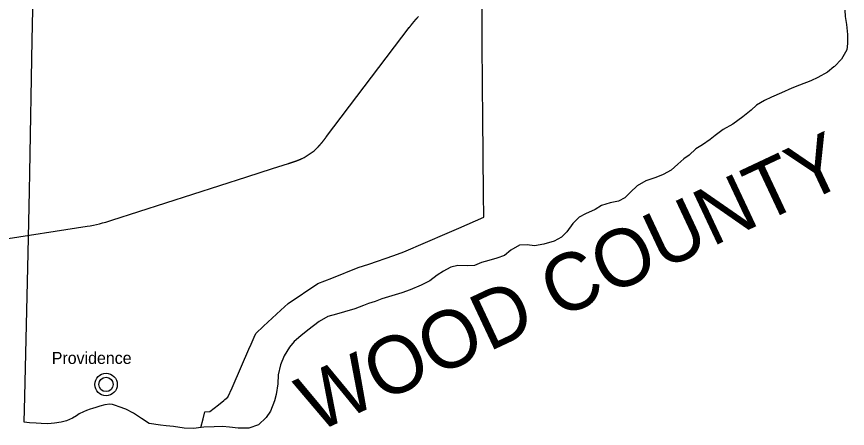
# Model space of a CAD drawing. Extents: x 0 to 750, y 0 to 507.
# Drawn here: x 114.5 to 187.1, y 53 to 88.9 of the extents above; entities that cross this region are included whole.
import ezdxf

# ---------------------------------------------------------------- set-up
doc = ezdxf.new("R2010")
doc.units = 0
for name, color, linetype in [('DV_X_Corp_Line', 7, 'Continuous'), ('GM_X_Adjacent_County_Text', 7, 'Continuous'), ('GM_X_County', 7, 'Continuous'), ('GM_X_State_Route', 7, 'Continuous'), ('GM_X_US_Route', 7, 'Continuous')]:
    doc.layers.add(name, color=color, linetype=linetype)

msp = doc.modelspace()

# ---------------------------------------------------------------- linework, layer by layer
at = {"layer": 'DV_X_Corp_Line'}
for radius in [0.982, 0.623]:
    msp.add_circle((122.35, 56.813), radius, dxfattribs=at)
at = {"layer": 'GM_X_County'}
msp.add_lwpolyline([(186.881, 89.488), (186.896, 88.92), (187.006, 88.235), (187.096, 87.36), (187.093, 86.581), (187.054, 86.01), (186.583, 85.214), (185.975, 84.582), (185.911, 84.53), (185.368, 84.085), (184.526, 83.617), (183.908, 83.307), (182.922, 82.952), (182.234, 82.672), (181.343, 82.281), (180.472, 81.884), (179.864, 81.598), (179.164, 81.184), (178.684, 80.755), (177.966, 80.165), (177.086, 79.533), (176.239, 79.075), (175.557, 78.555), (175.124, 78.206), (174.443, 77.731), (173.864, 77.374), (173.287, 76.842), (172.814, 76.504), (172.274, 76.036), (171.693, 75.524), (171.003, 75.145), (170.36, 74.875), (169.486, 74.584), (168.735, 74.15), (168.163, 73.593), (167.647, 73.09), (167.12, 72.813), (166.378, 72.66), (165.631, 72.432), (165.057, 72.071), (164.222, 71.714), (163.674, 71.413), (163.112, 70.851), (162.582, 70.127), (162.138, 69.683), (161.479, 69.334), (160.595, 69.073), (159.783, 68.912), (159.117, 69.009), (158.458, 68.986), (157.696, 68.522), (157.161, 68.07), (156.494, 67.831), (155.792, 67.628), (155.146, 67.454), (154.529, 67.199), (153.9, 67.17), (153.071, 67.184), (152.466, 67.06), (152.417, 67.033), (151.822, 66.71), (151.283, 66.348), (150.642, 65.853), (149.862, 65.48), (148.9, 65.066), (148.182, 64.813), (147.298, 64.547), (146.445, 64.286), (145.863, 64.051), (145.287, 63.89), (144.837, 63.708), (144.084, 63.425), (143.18, 63.155), (142.488, 62.956), (141.716, 62.739), (140.96, 62.31), (139.982, 61.555), (139.366, 61.069), (138.775, 60.557), (138.369, 60.068), (137.91, 59.313), (137.6, 58.52), (137.375, 57.661), (137.366, 56.858), (137.21, 55.932), (137.06, 55.368), (136.728, 54.47), (136.322, 53.919), (135.673, 53.288), (134.819, 53.006), (133.89, 52.987), (133.122, 53.07), (132.53, 53.131), (131.786, 53.113), (130.896, 53.078), (130.637, 53.048), (130.03, 52.977), (129.176, 52.997), (128.244, 53.128), (127.592, 53.189), (127.1, 53.258), (126.103, 53.41), (125.462, 53.828), (124.756, 54.307), (124.079, 54.66), (123.509, 54.87), (123.184, 54.976), (122.929, 55.051), (122.669, 55.09), (122.251, 55.022), (121.812, 54.919), (121.473, 54.809), (121.165, 54.704), (120.975, 54.653), (120.641, 54.55), (120.368, 54.42), (120.014, 54.245), (119.76, 54.069), (119.421, 53.875), (118.885, 53.648), (118.437, 53.526), (117.844, 53.446), (117.266, 53.381), (116.675, 53.411), (116.249, 53.424), (115.653, 53.464), (115.206, 53.52), (115.26, 55.748), (115.559, 68.28), (115.664, 73.723), (115.693, 75.284), (115.909, 86.877), (116.032, 93.503)], dxfattribs=at)
at = {"layer": 'GM_X_State_Route'}
for points in [[(155.354, 71.421), (155.329, 73.45), (155.248, 80.147), (155.215, 82.836), (155.214, 86.767), (155.212, 90.807), (155.211, 92.184), (155.207, 93.44), (155.186, 99.94), (155.186, 100.098), (155.203, 106.682), (155.204, 106.817)], [(130.832, 53.798), (130.993, 54.423)], [(130.637, 53.048), (130.832, 53.798)]]:
    msp.add_lwpolyline(points, dxfattribs=at)
at = {"layer": 'GM_X_US_Route'}
for p, q in [((141.619, 78.46), (148.832, 87.963)), ((134.648, 74.934), (136.884, 75.653)), ((136.884, 75.653), (138.299, 76.108)), ((122.858, 71.141), (134.648, 74.934)), ((98.126, 67.083), (120.692, 70.626))]:
    msp.add_line(p, q, dxfattribs=at)
for points in [[(153.169, 70.463), (155.354, 71.421)], [(134.833, 59.9), (135.018, 60.322), (135.286, 60.935), (135.429, 61.25), (136.102, 61.902), (137.608, 63.301), (138.26, 63.883), (140.858, 65.619), (142.065, 66.099), (144.368, 67.023), (145.296, 67.326), (147.494, 68.063), (148.365, 68.402), (152.157, 70.019), (153.169, 70.463)], [(133.355, 56.519), (133.442, 56.718), (134.833, 59.9)], [(132.636, 55.413), (132.736, 55.494), (133, 55.708), (133.355, 56.519)], [(130.993, 54.423), (131.405, 54.465), (132.167, 55.032), (132.636, 55.413)]]:
    msp.add_lwpolyline(points, dxfattribs=at)
for centre, radius, start, end in [((137.427, 80.858), 4.775, 295.33333, 315.29767), ((118.471, 84.776), 14.324, 278.92224, 287.83333)]:
    msp.add_arc(centre, radius, start, end, dxfattribs=at)
for points in [[(148.832, 87.963), (148.842, 87.976), (148.853, 87.989), (148.863, 88.003), (148.873, 88.016), (148.883, 88.03), (148.893, 88.043), (148.904, 88.057), (148.914, 88.07), (148.924, 88.084), (148.934, 88.097), (148.945, 88.11), (148.955, 88.124), (148.965, 88.137), (148.975, 88.151), (148.986, 88.164), (148.996, 88.177), (149.006, 88.191), (149.017, 88.204), (149.027, 88.218), (149.037, 88.231), (149.048, 88.244), (149.058, 88.258), (149.068, 88.271), (149.079, 88.284), (149.089, 88.298), (149.1, 88.311), (149.11, 88.324), (149.121, 88.337), (149.131, 88.351), (149.141, 88.364), (149.152, 88.377), (149.163, 88.39), (149.173, 88.404), (149.184, 88.417), (149.194, 88.43), (149.205, 88.443), (149.215, 88.456), (149.226, 88.469), (149.237, 88.482), (149.248, 88.495), (149.258, 88.508), (149.269, 88.521), (149.28, 88.534), (149.291, 88.547), (149.301, 88.56), (149.312, 88.573), (149.323, 88.586), (149.334, 88.599), (149.345, 88.612), (149.356, 88.625), (149.367, 88.638), (149.378, 88.65), (149.389, 88.663), (149.4, 88.676), (149.411, 88.689), (149.423, 88.701), (149.434, 88.714), (149.445, 88.727), (149.456, 88.739), (149.468, 88.752), (149.479, 88.764), (149.49, 88.777), (149.502, 88.789), (149.513, 88.801), (149.525, 88.814), (149.536, 88.826), (149.548, 88.838), (149.56, 88.851), (149.571, 88.863), (149.583, 88.875), (149.595, 88.887), (149.606, 88.899), (149.618, 88.911), (149.63, 88.924)], [(140.821, 77.499), (140.833, 77.511), (140.845, 77.523), (140.857, 77.535), (140.868, 77.548), (140.88, 77.56), (140.892, 77.572), (140.903, 77.584), (140.915, 77.597), (140.926, 77.609), (140.938, 77.621), (140.949, 77.634), (140.961, 77.646), (140.972, 77.659), (140.983, 77.671), (140.995, 77.684), (141.006, 77.696), (141.017, 77.709), (141.029, 77.722), (141.04, 77.734), (141.051, 77.747), (141.062, 77.76), (141.073, 77.772), (141.084, 77.785), (141.095, 77.798), (141.106, 77.811), (141.117, 77.824), (141.128, 77.837), (141.139, 77.849), (141.15, 77.862), (141.161, 77.875), (141.171, 77.888), (141.182, 77.901), (141.193, 77.914), (141.204, 77.927), (141.214, 77.94), (141.225, 77.954), (141.236, 77.967), (141.246, 77.98), (141.257, 77.993), (141.268, 78.006), (141.278, 78.019), (141.289, 78.032), (141.299, 78.046), (141.31, 78.059), (141.32, 78.072), (141.331, 78.085), (141.341, 78.099), (141.352, 78.112), (141.362, 78.125), (141.372, 78.138), (141.383, 78.152), (141.393, 78.165), (141.403, 78.178), (141.414, 78.192), (141.424, 78.205), (141.435, 78.219), (141.445, 78.232), (141.455, 78.245), (141.465, 78.259), (141.476, 78.272), (141.486, 78.286), (141.496, 78.299), (141.506, 78.312), (141.517, 78.326), (141.527, 78.339), (141.537, 78.353), (141.547, 78.366), (141.558, 78.38), (141.568, 78.393), (141.578, 78.406), (141.588, 78.42), (141.599, 78.433), (141.609, 78.447), (141.619, 78.46)], [(138.299, 76.108), (138.315, 76.114), (138.331, 76.119), (138.347, 76.124), (138.363, 76.129), (138.38, 76.134), (138.396, 76.139), (138.412, 76.145), (138.428, 76.15), (138.444, 76.155), (138.46, 76.16), (138.476, 76.165), (138.492, 76.171), (138.508, 76.176), (138.524, 76.181), (138.54, 76.186), (138.556, 76.192), (138.572, 76.197), (138.588, 76.202), (138.604, 76.208), (138.62, 76.213), (138.636, 76.218), (138.652, 76.224), (138.669, 76.229), (138.685, 76.234), (138.701, 76.24), (138.717, 76.245), (138.733, 76.251), (138.749, 76.256), (138.764, 76.262), (138.78, 76.267), (138.796, 76.273), (138.812, 76.278), (138.828, 76.284), (138.844, 76.289), (138.86, 76.295), (138.876, 76.301), (138.892, 76.306), (138.908, 76.312), (138.924, 76.318), (138.94, 76.323), (138.956, 76.329), (138.971, 76.335), (138.987, 76.341), (139.003, 76.347), (139.019, 76.353), (139.035, 76.359), (139.05, 76.365), (139.066, 76.371), (139.082, 76.377), (139.098, 76.383), (139.113, 76.389), (139.129, 76.395), (139.145, 76.401), (139.161, 76.408), (139.176, 76.414), (139.192, 76.42), (139.208, 76.427), (139.223, 76.433), (139.239, 76.44), (139.254, 76.446), (139.27, 76.453), (139.285, 76.459), (139.301, 76.466), (139.317, 76.473), (139.332, 76.479), (139.347, 76.486), (139.363, 76.493), (139.378, 76.5), (139.394, 76.507), (139.409, 76.514), (139.424, 76.521), (139.44, 76.528), (139.455, 76.535), (139.47, 76.542)]]:
    msp.add_spline(points, degree=3, dxfattribs=at)

# ---------------------------------------------------------------- texts
at = {"layer": 'DV_X_Corp_Line'}
msp.add_text('Providence', height=1.0417, rotation=0.00001, dxfattribs=at).set_placement((117.612, 58.603))
at = {"layer": 'GM_X_Adjacent_County_Text'}
msp.add_text('WOOD COUNTY', height=5, rotation=25.17903, dxfattribs=at).set_placement((140.645, 52.526))

doc.saveas('drawing.dxf')
